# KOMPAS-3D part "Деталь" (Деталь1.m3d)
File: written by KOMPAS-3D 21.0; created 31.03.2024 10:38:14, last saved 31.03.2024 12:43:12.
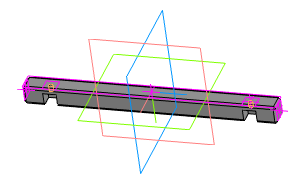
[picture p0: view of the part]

Document properties: Автор: Школа; Полное имя файла: C:\Users\Школа\Desktop\КУБСАТ ПРЕДПРОФФ\Контур.m3d

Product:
- Part/product: Деталь
    Масса: 0.05997

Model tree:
1. Эскиз:2
2. Элемент выдавливания:1
     Расстояние 1 = 2.5
3. Элемент выдавливания:2
     Расстояние 1 = 8.5
4. Отверстие:1  (with: Элемент выдавливания:1, Элемент выдавливания:2)  (labels: M2)
     Глубина выреза = 2.5; Диаметр отверстия = 1.56699; Угол конуса дна = 118; Расстояние 1 = 12; Расстояние 2 = 5.5
5. M2  (with: Элемент выдавливания:1)  (labels: cil0_24705-2004 coarse)
     Длина резьбы = 2.5; Шаг резьбы = 0.4; Номинальный диаметр резьбы = 2
6. Зеркальный массив:1
7. Экземпляр ( 1 )
8. Экземпляр ( 2 )  (with: Отверстие:1)
9. Скругление:1  (with: Элемент выдавливания:1, Элемент выдавливания:2)
     Радиус = 1
10. Эскиз:3  (with: Элемент выдавливания:2, Скругление:1)
11. Фаска:1  (with: Элемент выдавливания:2)
     Угол = 45; Длина 1 = 1; Длина 2 = 1
12. Эскиз:4  (with: Элемент выдавливания:2, Скругление:1)
13. Фаска:2  (with: Элемент выдавливания:2)
     Угол = 45; Длина 1 = 1; Длина 2 = 1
